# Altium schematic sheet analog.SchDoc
size A3; Date: Not shown in title block; ApprovedBy: Not shown in title block; CheckedBy: Not shown in title block; Author: Not shown in title block; CompanyName: Not shown in title block; Engineer: Not shown in title block; Organization: Not shown in title block; Address1: Not shown in title block; Address2: Not shown in title block; Address3: Not shown in title block; Address4: Not shown in title block; DocumentNumber: 2; Revision: Use project parameter SCH_Rev; SheetNumber: 2; SheetTotal: 3; PageSetup: Record=PageOptions¦CenterHorizontal=True¦CenterVertical=True¦PrintScale=1.00¦XCorrection=1.00¦YCorrection=1.00¦PrintKind=0¦BorderSize=5000000¦LeftOffset=0¦BottomOffset=0¦Orientation=2¦PaperLength=1000¦PaperWidth=1000¦Scale=100¦PaperSource=15¦PrintQuality=600¦MediaType=1¦DitherType=10¦PaperKind=Letter¦PrintScaleMode=1
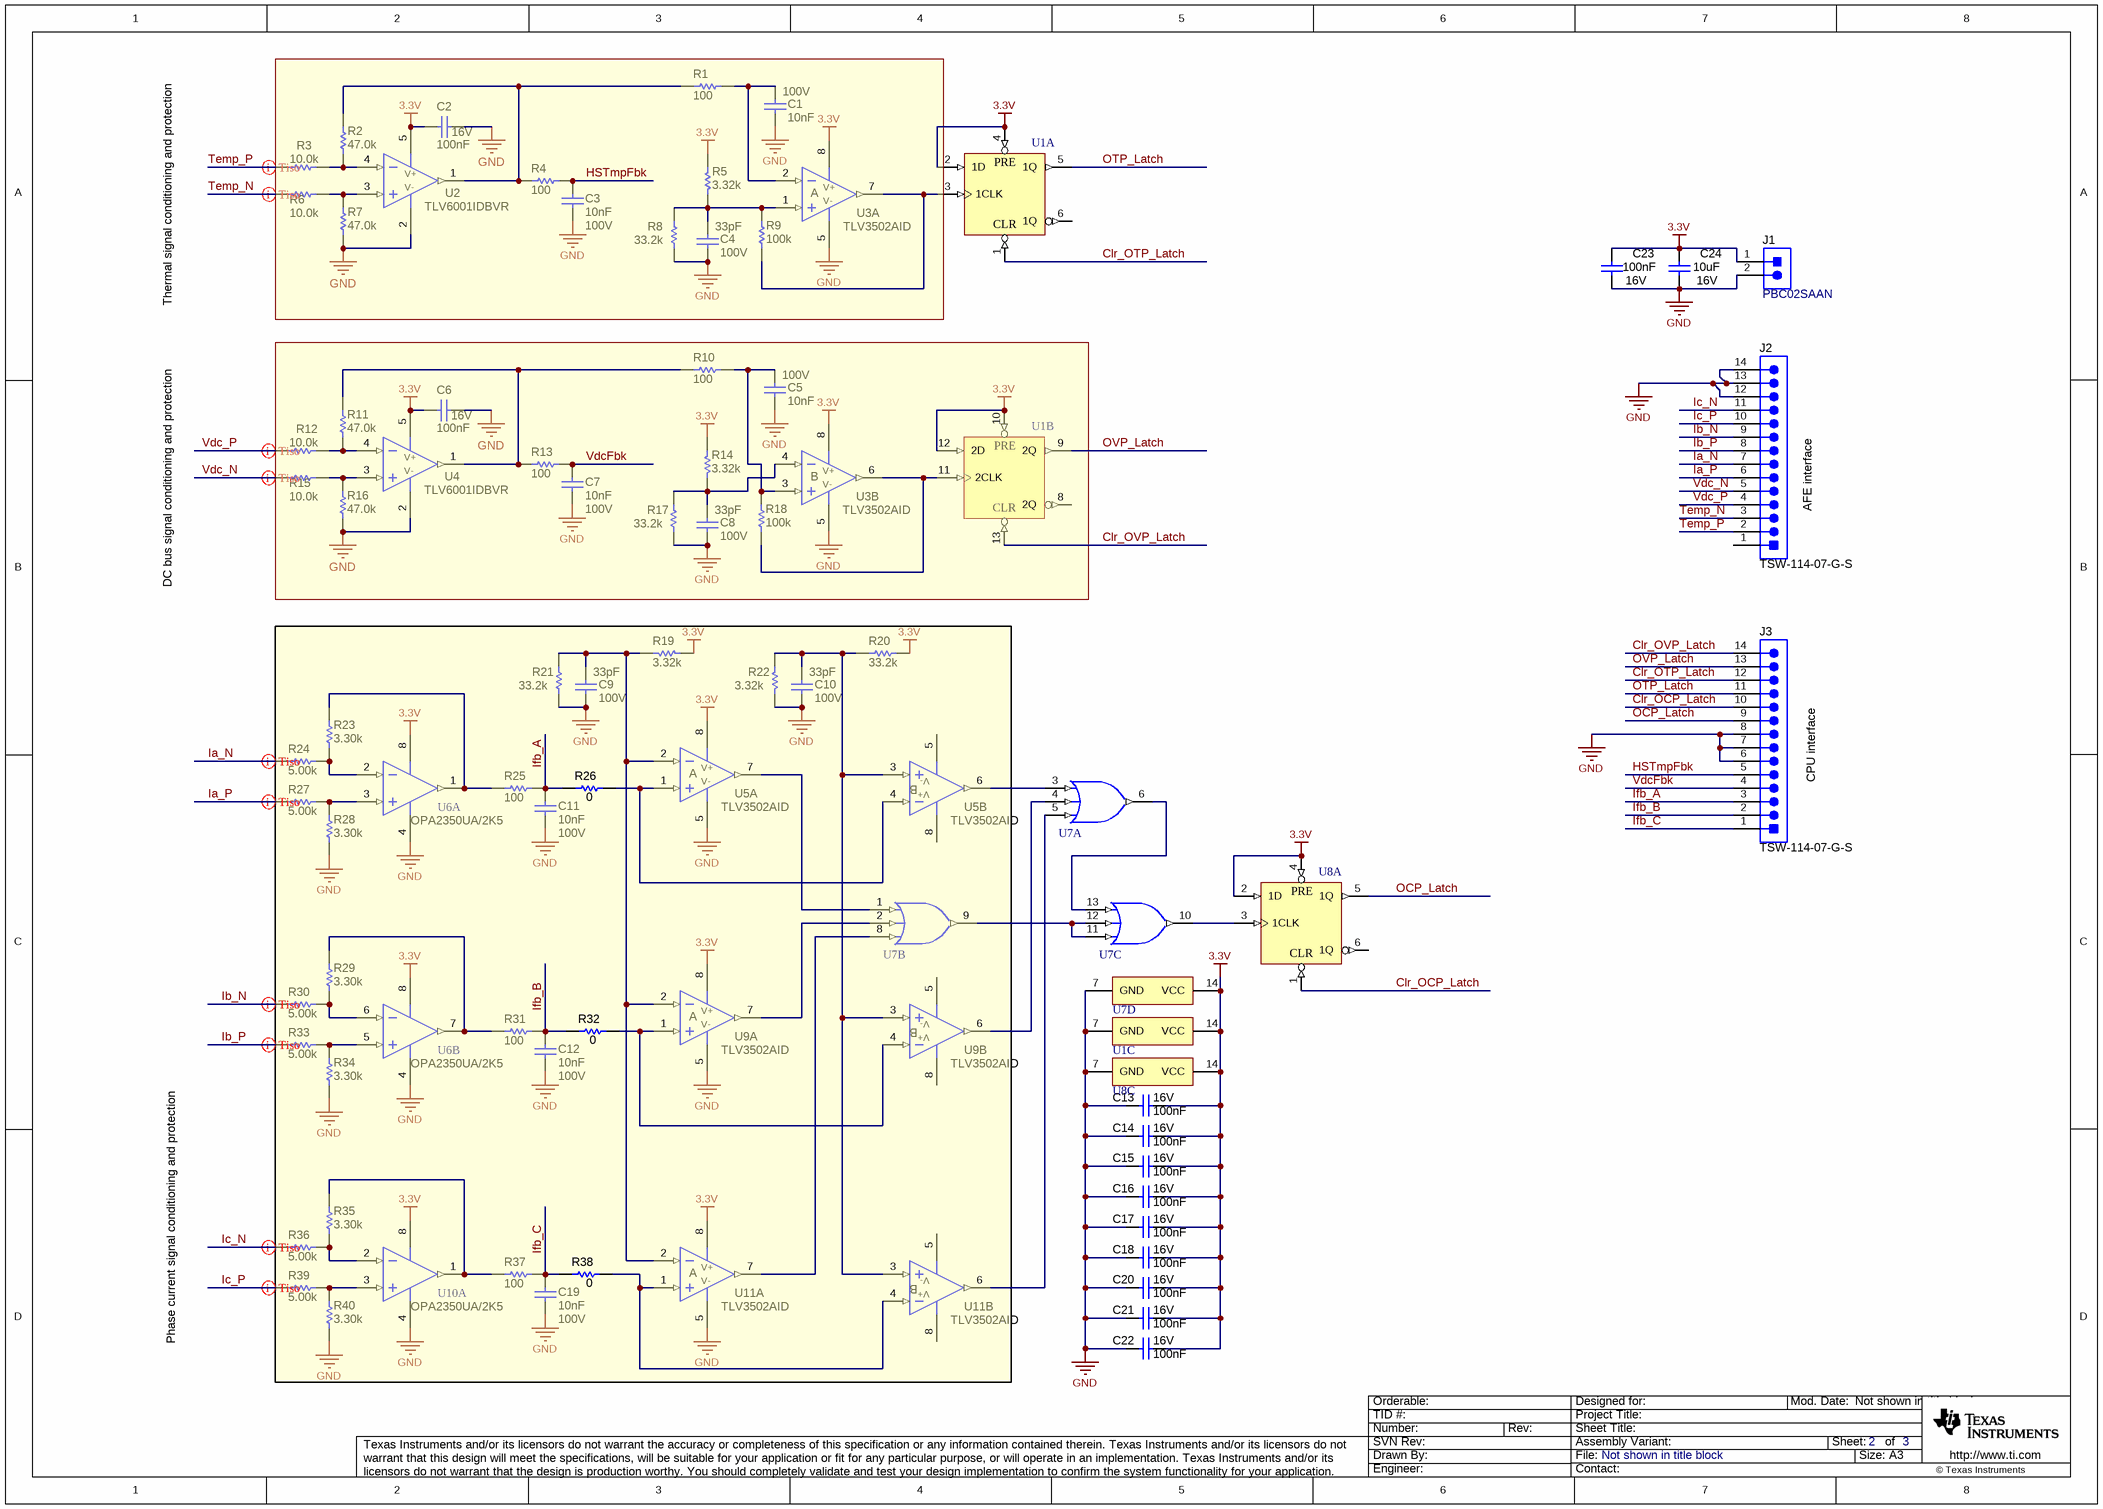
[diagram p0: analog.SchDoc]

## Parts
C1  Cap_F: 10nF  VDC_V: 100V  [0805_HV]  (hidden comment: 08051C103JAT2A)
C2  Cap_F: 100nF  VDC_V: 16V  [0805_HV]  (hidden comment: GRM219R71C104KA01D)
C3  Cap_F: 10nF  VDC_V: 100V  [0805_HV]  (hidden comment: 08051C103JAT2A)
C4  VDC_V: 100V  ValueDisplayed: 33pF  [0805_HV]  (hidden comment: 08051A330JAT2A)
C5  Cap_F: 10nF  VDC_V: 100V  [0805_HV]  (hidden comment: 08051C103JAT2A)
C6  Cap_F: 100nF  VDC_V: 16V  [0805_HV]  (hidden comment: GRM219R71C104KA01D)
C7  Cap_F: 10nF  VDC_V: 100V  [0805_HV]  (hidden comment: 08051C103JAT2A)
C8  VDC_V: 100V  ValueDisplayed: 33pF  [0805_HV]  (hidden comment: 08051A330JAT2A)
C9  VDC_V: 100V  ValueDisplayed: 33pF  [0805_HV]  (hidden comment: 08051A330JAT2A)
C10  VDC_V: 100V  ValueDisplayed: 33pF  [0805_HV]  (hidden comment: 08051A330JAT2A)
C11  Cap_F: 10nF  VDC_V: 100V  [0805_HV]  (hidden comment: 08051C103JAT2A)
C12  Cap_F: 10nF  VDC_V: 100V  [0805_HV]  (hidden comment: 08051C103JAT2A)
C13  Cap_F: 100nF  VDC_V: 16V  [0805_HV]  (hidden comment: GRM219R71C104KA01D)
C14  Cap_F: 100nF  VDC_V: 16V  [0805_HV]  (hidden comment: GRM219R71C104KA01D)
C15  Cap_F: 100nF  VDC_V: 16V  [0805_HV]  (hidden comment: GRM219R71C104KA01D)
C16  Cap_F: 100nF  VDC_V: 16V  [0805_HV]  (hidden comment: GRM219R71C104KA01D)
C17  Cap_F: 100nF  VDC_V: 16V  [0805_HV]  (hidden comment: GRM219R71C104KA01D)
C18  Cap_F: 100nF  VDC_V: 16V  [0805_HV]  (hidden comment: GRM219R71C104KA01D)
C19  Cap_F: 10nF  VDC_V: 100V  [0805_HV]  (hidden comment: 08051C103JAT2A)
C20  Cap_F: 100nF  VDC_V: 16V  [0805_HV]  (hidden comment: GRM219R71C104KA01D)
C21  Cap_F: 100nF  VDC_V: 16V  [0805_HV]  (hidden comment: GRM219R71C104KA01D)
C22  Cap_F: 100nF  VDC_V: 16V  [0805_HV]  (hidden comment: GRM219R71C104KA01D)
C23  Cap_F: 100nF  VDC_V: 16V  [0805_HV]  (hidden comment: GRM219R71C104KA01D)
C24  VDC_V: 16V  ValueDisplayed: 10uF  [0805_HV]  (hidden comment: 0805YD106MAT2A)
J1  PBC02SAAN  [Sullins_PBC02SAAN]
J2  TSW-114-07-G-S  [TSW-114-07-G-S]
J3  TSW-114-07-G-S  [TSW-114-07-G-S]
R1  ValueDisplayed: 100  [0805_HV]  (hidden comment: CRCW0805100RDHEAP)
R2  ValueDisplayed: 47.0k  [0805_HV]  (hidden comment: RT0805BRD0747KL)
R3  ValueDisplayed: 10.0k  [0805_HV]  (hidden comment: RG2012P-103-B-T5)
R4  ValueDisplayed: 100  [0805_HV]  (hidden comment: CRCW0805100RDHEAP)
R5  ValueDisplayed: 3.32k  [0805_HV]  (hidden comment: RR1220P-3321-D-M)
R6  ValueDisplayed: 10.0k  [0805_HV]  (hidden comment: RG2012P-103-B-T5)
R7  ValueDisplayed: 47.0k  [0805_HV]  (hidden comment: RT0805BRD0747KL)
R8  ValueDisplayed: 33.2k  [0805_HV]  (hidden comment: RG2012P-3322-B-T5)
R9  ValueDisplayed: 100k  [0805_HV]  (hidden comment: RR1220P-104-D)
R10  ValueDisplayed: 100  [0805_HV]  (hidden comment: CRCW0805100RDHEAP)
R11  ValueDisplayed: 47.0k  [0805_HV]  (hidden comment: RT0805BRD0747KL)
R12  ValueDisplayed: 10.0k  [0805_HV]  (hidden comment: RG2012P-103-B-T5)
R13  ValueDisplayed: 100  [0805_HV]  (hidden comment: CRCW0805100RDHEAP)
R14  ValueDisplayed: 3.32k  [0805_HV]  (hidden comment: RR1220P-3321-D-M)
R15  ValueDisplayed: 10.0k  [0805_HV]  (hidden comment: RG2012P-103-B-T5)
R16  ValueDisplayed: 47.0k  [0805_HV]  (hidden comment: RT0805BRD0747KL)
R17  ValueDisplayed: 33.2k  [0805_HV]  (hidden comment: RG2012P-3322-B-T5)
R18  ValueDisplayed: 100k  [0805_HV]  (hidden comment: RR1220P-104-D)
R19  ValueDisplayed: 3.32k  [0805_HV]  (hidden comment: RR1220P-3321-D-M)
R20  ValueDisplayed: 33.2k  [0805_HV]  (hidden comment: RG2012P-3322-B-T5)
R21  ValueDisplayed: 33.2k  [0805_HV]  (hidden comment: RG2012P-3322-B-T5)
R22  ValueDisplayed: 3.32k  [0805_HV]  (hidden comment: RR1220P-3321-D-M)
R23  ValueDisplayed: 3.30k  [0805_HV]  (hidden comment: RG2012P-332-B-T5)
R24  ValueDisplayed: 5.00k  [0805_HV]  (hidden comment: PNM0805E5001BST5)
R25  ValueDisplayed: 100  [0805_HV]  (hidden comment: CRCW0805100RDHEAP)
R26  ValueDisplayed: 0  [0603_HV]  (hidden comment: RC0603JR-070RL)
R27  ValueDisplayed: 5.00k  [0805_HV]  (hidden comment: PNM0805E5001BST5)
R28  ValueDisplayed: 3.30k  [0805_HV]  (hidden comment: RG2012P-332-B-T5)
R29  ValueDisplayed: 3.30k  [0805_HV]  (hidden comment: RG2012P-332-B-T5)
R30  ValueDisplayed: 5.00k  [0805_HV]  (hidden comment: PNM0805E5001BST5)
R31  ValueDisplayed: 100  [0805_HV]  (hidden comment: CRCW0805100RDHEAP)
R32  ValueDisplayed: 0  [0603_HV]  (hidden comment: RC0603JR-070RL)
R33  ValueDisplayed: 5.00k  [0805_HV]  (hidden comment: PNM0805E5001BST5)
R34  ValueDisplayed: 3.30k  [0805_HV]  (hidden comment: RG2012P-332-B-T5)
R35  ValueDisplayed: 3.30k  [0805_HV]  (hidden comment: RG2012P-332-B-T5)
R36  ValueDisplayed: 5.00k  [0805_HV]  (hidden comment: PNM0805E5001BST5)
R37  ValueDisplayed: 100  [0805_HV]  (hidden comment: CRCW0805100RDHEAP)
R38  ValueDisplayed: 0  [0603_HV]  (hidden comment: RC0603JR-070RL)
R39  ValueDisplayed: 5.00k  [0805_HV]  (hidden comment: PNM0805E5001BST5)
R40  ValueDisplayed: 3.30k  [0805_HV]  (hidden comment: RG2012P-332-B-T5)
U1  SN74LVC74AQPWRQ1  [PW0014A_N]  (value not drawn)  (parts A,B,C of 3)
U2  TLV6001IDBVR  [DBV0005A_N]
U3  TLV3502AID  [D0008A_N]  (parts A,B of 2)
U4  TLV6001IDBVR  [DBV0005A_N]
U5  TLV3502AID  [D0008A_N]  (parts A,B of 2)
U6  OPA2350UA/2K5  [D0008A_N]  (parts A,B of 2)
U7  CD74HC4075MT  [D0014A_N]  (value not drawn)  (parts A,B,C,D of 4)
U8  SN74LVC74AQPWRQ1  [PW0014A_N]  (value not drawn)  (parts A,C of 3)
U9  TLV3502AID  [D0008A_N]  (parts A,B of 2)
U10  OPA2350UA/2K5  [D0008A_N]  (part A of 2)
U11  TLV3502AID  [D0008A_N]  (parts A,B of 2)

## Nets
3.3V: C2.1 C6.1 C13.2 C14.2 C15.2 C16.2 C17.2 C18.2 C20.2 C21.2 C22.2 C23.2 C24.1 J1.1 R5.2 R14.2 R19.2 R20.2 U1.2(1D) U1.4(1~{PRE}) U1.10(2~{PRE}) U1.12(2D) U1.14(VCC) U2.5(V+) U3.8(V+) U4.5(V+) U5.8(V+) U6.8(V+) U7.14(VCC) U8.2(1D) U8.4(1~{PRE}) U8.14(VCC) U9.8(V+) U10.8(V+) U11.8(V+)
GND: C1.2 C2.2 C3.2 C4.2 C5.2 C6.2 C7.2 C8.2 C9.2 C10.2 C11.2 C12.2 C13.1 C14.1 C15.1 C16.1 C17.1 C18.1 C19.2 C20.1 C21.1 C22.1 C23.1 C24.2 J1.2 J2.12 J2.13 J2.14 J3.6 J3.7 J3.8 R7.1 R8.1 R16.1 R17.1 R21.1 R22.2 R28.1 R34.1 R40.1 U1.7(GND) U2.2(V-) U3.5(V-) U4.2(V-) U5.5(V-) U6.4(V-) U7.7(GND) U8.7(GND) U9.5(V-) U10.4(V-) U11.5(V-)
Clr_OCP_Latch: J3.10 U8.1(1~{CLR})
Clr_OTP_Latch: J3.12 U1.1(1~{CLR})
Clr_OVP_Latch: J3.14 U1.13(2~{CLR})
HSTmpFbk: C3.1 J3.5 R4.2
Ia_N: J2.7 R24.1
Ia_P: J2.6 R27.1
Ib_N: J2.9 R30.1
Ib_P: J2.8 R33.1
Ic_N: J2.11 R36.1
Ic_P: J2.10 R39.1
Ifb_A: C11.1 J3.3 R25.2 R26.2
Ifb_B: C12.1 J3.2 R31.2 R32.2
Ifb_C: C19.1 J3.1 R37.2 R38.2
OCP_Latch: J3.9 U8.5(1Q)
OTP_Latch: J3.11 U1.5(1Q)
OVP_Latch: J3.13 U1.9(2Q)
Temp_N: J2.3 R6.1
Temp_P: J2.2 R3.1
Vdc_N: J2.5 R15.1
Vdc_P: J2.4 R12.1
VdcFbk: C7.1 J3.4 R13.2
NetC1_1: C1.1 R1.2 U3.2(-IN_A)
NetC4_1: C4.1 R5.1 R8.2 R9.2 U3.1(+IN_A)
NetC5_1: C5.1 R10.2 R18.2 U3.3(+IN_B)
NetC8_1: C8.1 R14.1 R17.2 U3.4(-IN_B)
NetC9_1: C9.1 R19.1 R21.2 U5.2(-IN_A) U9.2(-IN_A) U11.2(-IN_A)
NetC10_1: C10.1 R20.1 R22.1 U5.3(+IN_B) U9.3(+IN_B) U11.3(+IN_B)
NetR1_1: R1.1 R2.2 R4.1 U2.1(OUT)
NetR2_1: R2.1 R3.2 U2.4(IN-)
NetR6_2: R6.2 R7.2 U2.3(IN+)
NetR9_1: R9.1 U1.3(1CLK) U3.7(OUT_A)
NetR10_1: R10.1 R11.2 R13.1 U4.1(OUT)
NetR11_1: R11.1 R12.2 U4.4(IN-)
NetR15_2: R15.2 R16.2 U4.3(IN+)
NetR18_1: R18.1 U1.11(2CLK) U3.6(OUT_B)
NetR23_1: R23.1 R24.2 U6.2(IN_A-)
NetR23_2: R23.2 R25.1 U6.1(OUT_A)
NetR26_1: R26.1 U5.1(+IN_A) U5.4(-IN_B)
NetR27_2: R27.2 R28.2 U6.3(IN_A+)
NetR29_1: R29.1 R30.2 U6.6(IN_B-)
NetR29_2: R29.2 R31.1 U6.7(OUT_B)
NetR32_1: R32.1 U9.1(+IN_A) U9.4(-IN_B)
NetR33_2: R33.2 R34.2 U6.5(IN_B+)
NetR35_1: R35.1 R36.2 U10.2(IN_A-)
NetR35_2: R35.2 R37.1 U10.1(OUT_A)
NetR38_1: R38.1 U11.1(+IN_A) U11.4(-IN_B)
NetR39_2: R39.2 R40.2 U10.3(IN_A+)
NetU5_6: U5.6(OUT_B) U7.3(1A)
NetU5_7: U5.7(OUT_A) U7.1(2A)
NetU7_2: U7.2(2B) U9.7(OUT_A)
NetU7_4: U7.4(1B) U9.6(OUT_B)
NetU7_5: U7.5(1C) U11.6(OUT_B)
NetU7_6: U7.6(1Y) U7.13(3C)
NetU7_8: U7.8(2C) U11.7(OUT_A)
NetU7_9: U7.9(2Y) U7.11(3A) U7.12(3B)
NetU7_10: U7.10(3Y) U8.3(1CLK)

Not connected (* = marked no-connect by the designer): J2 1; U1 6(1Q) 8(2Q); U8 6(1Q)

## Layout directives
differential pair: Ia_N, Ia_P, Ib_N, Ib_P, Ic_N, Ic_P, Temp_N, Temp_P, Vdc_N, Vdc_P

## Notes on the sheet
- Thermal signal conditioning and protection
- DC bus signal conditioning and protection
- (near J2) AFE interface
- (near J3) CPU interface
- Phase current signal conditioning and protection

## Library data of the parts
C1 C3 C5 C7 C11 C12 C19 = CMP-0007542-1: CAP, CERM, 0.01 uF, 100 V, +/- 5%, X7R, 0805; Manufacturer: AVX; TaMin_C: -55°C; ESR_ohm: 0.078; Polarized: N; SizeAreaWB_mm2: 6.75; Value1: 0.078 ohm; U/M: EA; Value: 0.01uF; TaMax_C: 125°C; SizeZ_mm: 1.45; SizeX_mm: 2; SizeY_mm: 1.25; Cap_Case: 0805; SizeArea_mm2: 2.5; AEC Category: Q200
C2 C6 C13-C18 C20-C23 = CMP-0008209-1: CAP, CERM, 0.1 uF, 16 V, +/- 10%, X7R, 0805; Manufacturer: MuRata; TaMin_C: -55°C; Polarized: N; SizeAreaWB_mm2: 6.75; Value1: Unknown; U/M: EA; Value: 0.1uF; TaMax_C: 125°C; SizeZ_mm: 1.45; SizeX_mm: 2; SizeY_mm: 1.25; Cap_Case: 0805; SizeArea_mm2: 2.5; AEC Category: Q200
C4 C8-C10 = CMP-0007529-1: CAP, CERM, 33 pF, 100 V, +/- 5%, C0G/NP0, 0805; Manufacturer: AVX; TaMin_C: -55°C; ESR_ohm: 0.708; Polarized: N; SizeAreaWB_mm2: 6.75; Value1: 0.708 ohm; U/M: EA; Value: 33pF; TaMax_C: 125°C; SizeZ_mm: 1.45; SizeX_mm: 2; SizeY_mm: 1.25; Cap_Case: 0805; SizeArea_mm2: 2.5; AEC Category: Q200
C24 = CMP-0007678-2: CAP, CERM, 10 uF, 16 V, +/- 20%, X5R, 0805; Manufacturer: AVX; TaMin_C: -55°C; Polarized: N; SizeAreaWB_mm2: 6.75; Value1: Unknown; U/M: EA; Value: 10uF; TaMax_C: 85°C; SizeZ_mm: 1.45; SizeX_mm: 2; SizeY_mm: 1.25; Cap_Case: 0805; SizeArea_mm2: 2.5; Cap_F: 10µF; AEC Category: Q200
J1 = CMP-0054566-1: Header, 100mil, 2x1, Gold, TH; Manufacturer: Sullins Connector Solutions; CNHeader: TRUE; Current_A: 3A; Green_Lifecycle: Active; Shrouded: N; Gender: Male; Green_REACh: Passed; Voltage_V: 1.8kV; Row_Count: 1; Pitch_mm: 2.54; CT: FALSE; Cert_UL: Y
J2 J3 = CMP-0075428-1: Header, 100mil, 14x1, Gold, TH; Manufacturer: Samtec; Pitch_mm: 2.54; Cert_VDE: N; Gender: Male; Cert_CSA: Y; Voltage_V: 550V; Green_REACh: Passed; Current_A: 6.3A; CT: False; Green_Lifecycle: Active; Row_Count: 1; CNHeader: True
R1 R4 R10 R13 R25 R31 R37 = CMP-0065350-1: RES, 100, .5%, .125 W, AEC-Q200 Grade 0, 0805; Manufacturer: Vishay-Dale; Power_W: 125mW; TempCo: 50 ppm/C; Value_Code: 100R; U/M: EA; Value: 100; EIA_Code: E192; Tolerance_%: 0.5%; SizeX_mm: 2.0; SizeY_mm: 1.25; SizeZ_mm: 1.45; Value2: .125W; SizeArea_mm2: 2.5; AEC Qualified: Y; AEC Grade: 0; AEC Category: Q200
R2 R7 R11 R16 = CMP-0020108-1: RES, 47.0 k, 0.1%, 0.125 W, 0805; Manufacturer: Yageo America; Power_W: 125mW; TempCo: 25 ppm/C; Value_Code: 47k0; U/M: EA; Value: 47.0k; EIA_Code: E192; Res_ohm: 47k; SizeX_mm: 2; SizeY_mm: 1.25; SizeZ_mm: 1.45; Value2: 0.125W; SizeArea_mm2: 2.5; VDC_V: 150V; AEC Category: Q200
R3 R6 R12 R15 = CMP-0018856-1: RES, 10.0 k, 0.1%, 0.125 W, 0805; Manufacturer: Susumu Co Ltd; Power_W: 125mW; TempCo: 25 ppm/C; Value_Code: 10k0; U/M: EA; Value: 10.0k; EIA_Code: E192; Res_ohm: 10k; SizeX_mm: 2; SizeY_mm: 1.25; SizeZ_mm: 1.45; Value2: 0.125W; SizeArea_mm2: 2.5; VDC_V: 100V; AEC Category: Q200
R5 R14 R19 R22 = CMP-0019250-1: RES, 3.32 k, 0.5%, 0.1 W, 0805; Manufacturer: Susumu Co Ltd; Power_W: 100mW; TempCo: 25 ppm/C; Value_Code: 3k32; U/M: EA; Value: 3.32k; EIA_Code: E192; SizeX_mm: 2; SizeY_mm: 1.25; SizeZ_mm: 1.45; Value2: 0.1W; SizeArea_mm2: 2.5; VDC_V: 100V; AEC Category: Q200
R8 R17 R20 R21 = CMP-0018959-1: RES, 33.2 k, 0.1%, 0.125 W, 0805; Manufacturer: Susumu Co Ltd; Power_W: 125mW; TempCo: 25 ppm/C; Value_Code: 33k2; U/M: EA; Value: 33.2k; EIA_Code: E192; SizeX_mm: 2; SizeY_mm: 1.25; SizeZ_mm: 1.45; Value2: 0.125W; SizeArea_mm2: 2.5; VDC_V: 100V; AEC Category: Q200
R9 R18 = CMP-0019096-1: RES, 100 k, 0.5%, 0.1 W, 0805; Manufacturer: Susumu Co Ltd; Power_W: 100mW; TempCo: 25 ppm/C; U/M: EA; Value: 100k; EIA_Code: E192; SizeX_mm: 2; SizeY_mm: 1.25; SizeZ_mm: 1.45; Value2: 0.1W; SizeArea_mm2: 2.5; VDC_V: 100V; AEC Category: Q200
R23 R28 R29 R34 R35 R40 = CMP-0018960-1: RES, 3.30 k, 0.1%, 0.125 W, 0805; Manufacturer: Susumu Co Ltd; Power_W: 125mW; TempCo: 25 ppm/C; Value_Code: 3k30; U/M: EA; Value: 3.30k; Res_ohm: 3.3k; SizeX_mm: 2; SizeY_mm: 1.25; SizeZ_mm: 1.45; Value2: 0.125W; SizeArea_mm2: 2.5; VDC_V: 100V; AEC Category: Q200
R24 R27 R30 R33 R36 R39 = CMP-0018848-1: RES, 5.00 k, 0.1%, 0.2 W, 0805; Manufacturer: Vishay Thin Film; Power_W: 200mW; TempCo: 25 ppm/C; Value_Code: 5k00; U/M: EA; Value: 5.00k; Res_ohm: 5k; SizeX_mm: 2; SizeY_mm: 1.25; SizeZ_mm: 1.45; Value2: 0.2W; SizeArea_mm2: 2.5; AEC Qualified: N; VDC_V: 100V; AEC Category: Q200
R26 R32 R38 = CMP-0025885-5: RES, 0, 5%, 0.1 W, 0603; Manufacturer: Yageo; Value: 0; Value_Code: 0000; Power_W: 100mW; Value2: 0.1W; VDC_V: 75V; TempCo: 200 ppm/C; EIA_Code: E24; AEC Category: Q200; AEC Qualified: N; SizeArea_mm2: 1.28; SizeX_mm: 1.6; SizeY_mm: 0.8; SizeZ_mm: 1; SizeAreaWB_mm2: 4.68
U1 U8 = CMP-0048843-1: Automotive Catalog Dual Positive-Edge-Triggered D-Type Flip-Flops With Clear And Preset, PW0014A, LARGE T&R; Generic Part Number: SN74LVC74A-Q1; Manufacturer: Texas Instruments; VCC(Min)(V): 2; Schmitt Trigger: No; Input Type: TTL,CMOS; tpd @ Nom Voltage(Max)(ns): 6,5.2; VCC(Max)(V): 3.6; Output Drive (IOL/IOH)(Max)(mA): 24/-24; F @ Nom Voltage(Max)(Mhz): 100; Technology Family: LVC; Voltage(Nom)(V): 2.7,3.3; ICC @ Nom Voltage(Max)(mA): 0.01; Output Type: LVTTL
U2 U4 = CMP-0073547-1: 1-MHz, Low-Power Operational Amplifier for Cost-Sensitive Systems, DBV0005A (SOT-23-5); Alternate PartNumber: TLV6001IDBVT; Alternate Manufacturer: Texas Instruments; SizeAreaWB_mm2: 14.82; U/M: EA; SizeZ_mm: 1.45; SizeX_mm: 2.8; SizeY_mm: 2.9; SizeArea_mm2: 8.12; CompType: IC
U3 U5 U9 U11 = CMP-0065423-1: 4.5ns Rail-to-Rail Comparator, D0008A (SOIC-8); Alternate Manufacturer: Texas Instruments; SizeAreaWB_mm2: 56.58; U/M: EA; SizeZ_mm: 1.75; SizeX_mm: 4.9; SizeY_mm: 6.2; SizeArea_mm2: 30.38; CompType: IC
U6 U10 = CMP-0040782-1: High-Speed, Single-Supply, Rail-to-Rail Operational Amplifier MicroAmplifier(TM) Series, 2.7 to 5.5 V, -40 to 85 degC, 8-pin SOIC (D8), Green (RoHS & no Sb/Br); Manufacturer: Texas Instruments; Sub Family: Low Input Bias Current Amp (<=10pA), Low Offset Voltage Amplifier (<=500uV), Low Supply Voltage Amplifier (<=2.7V), Precision Amplifier; Offset Drift(Typ)(uV/C): 4; Vn at 1kHz(Typ)(nV/rtHz): 18; Number of Channels: 2; Total Supply Voltage(Min)(+5V is 5, +/-5V is 10): 2.7; Vio (25C)(Max)(mV): 1; Iq per channel(Max)(mA): 8.5; Total Supply Voltage(Max)(+5V is 5, +/-5V is 10): 5.5; IIB(Max)(pA): 10; CMRR(Min)(dB): 74; Slew Rate(Typ)(V/us): 22
U7 = CMP-0050748-1: High Speed CMOS Logic Triple 3-Input OR Gates, D0014A, SMALL T&R; Manufacturer: Texas Instruments; VCC(Max)(V): 6; F @ Nom Voltage(Max)(Mhz): 70; VCC(Min)(V): 2; ICC @ Nom Voltage(Max)(mA): 0.02; Output Drive (IOL/IOH)(Max)(mA): 5.2/-5.2; Bits(#): 3; tpd @ Nom Voltage(Max)(ns): 25; Voltage(Nom)(V): 5; Rating: Catalog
